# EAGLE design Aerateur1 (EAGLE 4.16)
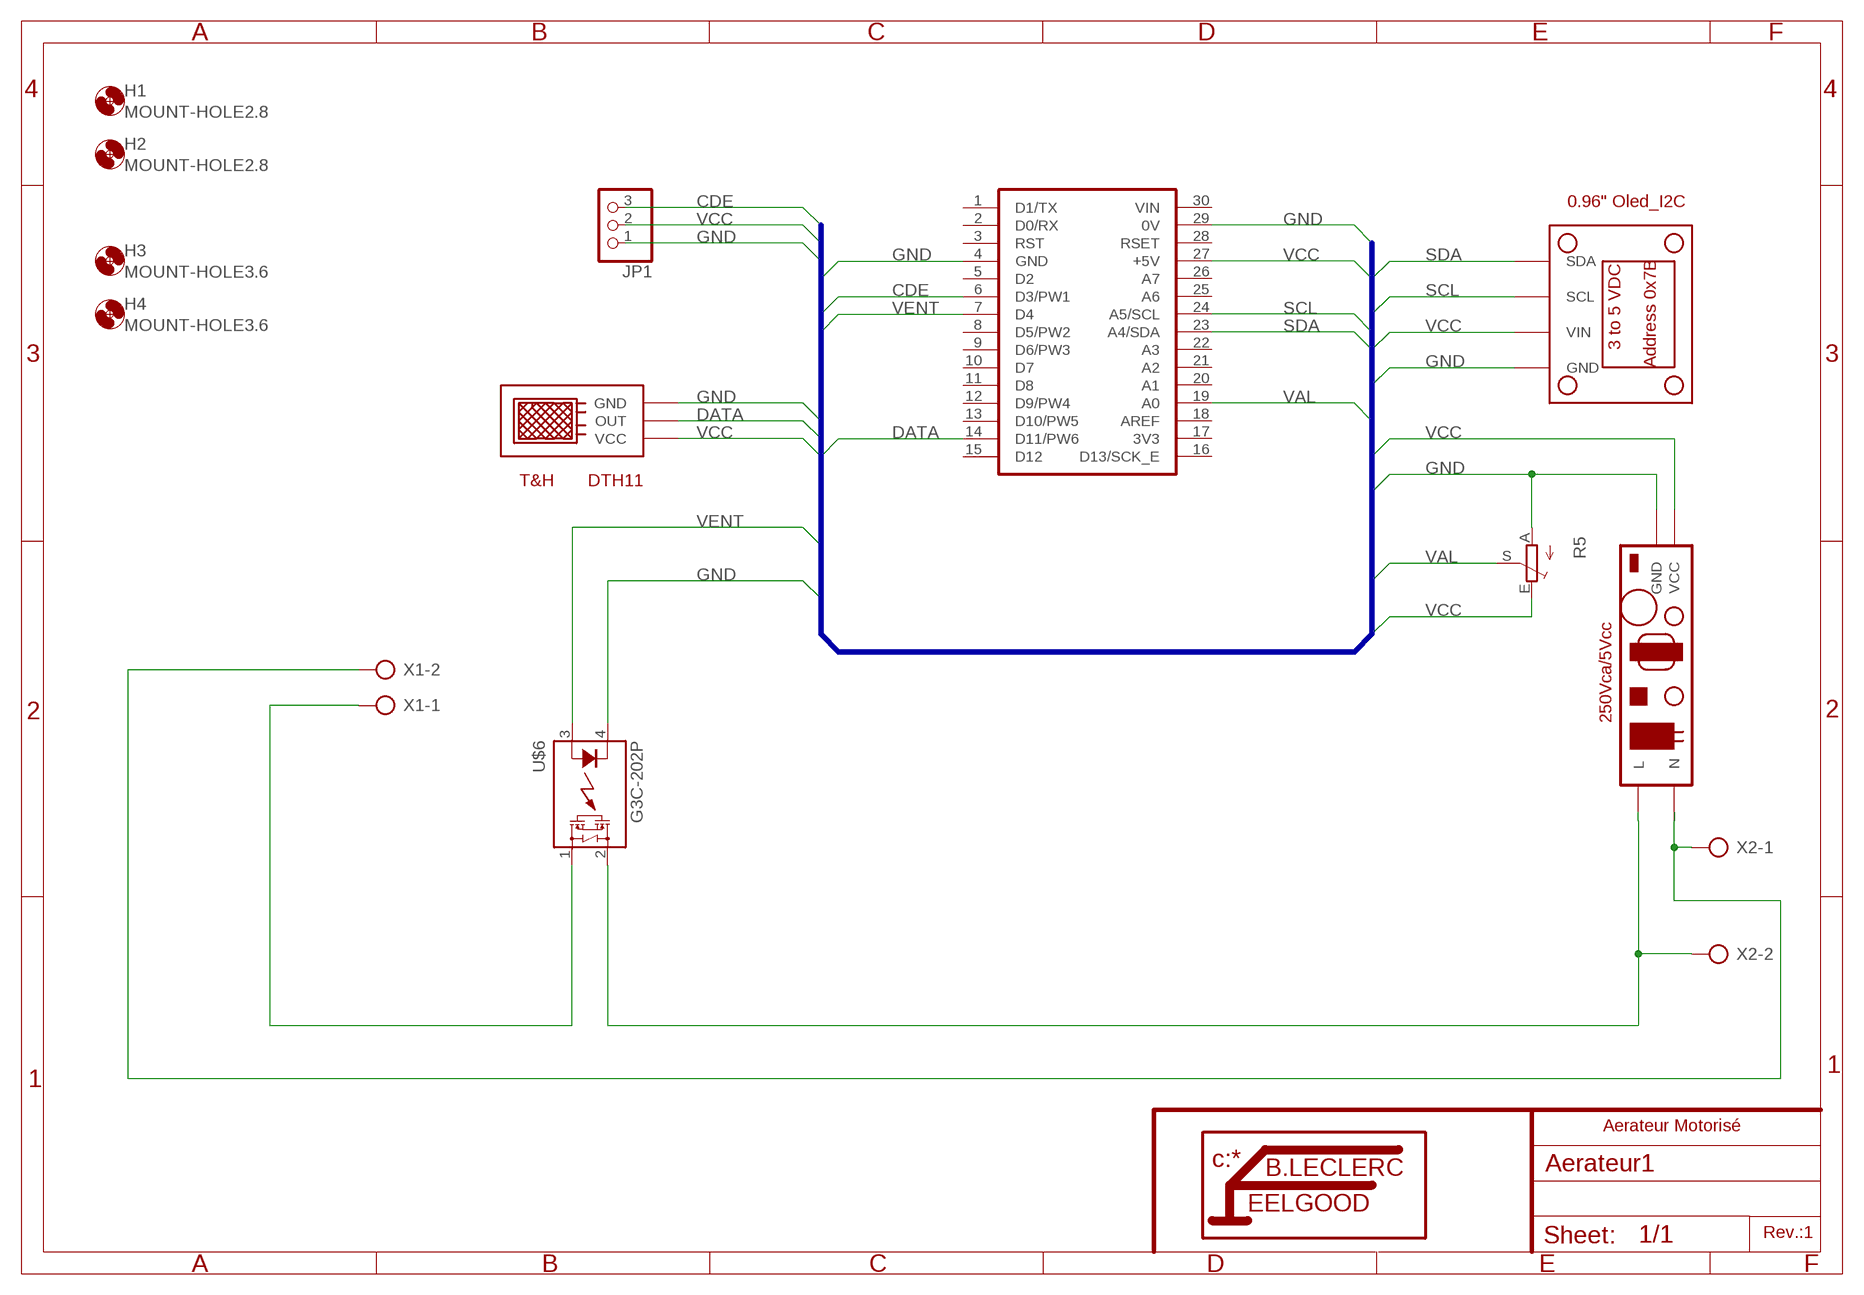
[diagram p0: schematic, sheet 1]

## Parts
H1  MOUNT-HOLE2.8  [2,8]
H2  MOUNT-HOLE2.8  [2,8]
H3  MOUNT-HOLE3.6  [3,6]
H4  MOUNT-HOLE3.6  [3,6]
JP1  PINHD-1X3  [1X03]
R5  TRIM_EU-S63S  [S63S]
U1  NANO  [NANO]
U$2  SWPWR250-5ALIM  [SWPWR250-5ALIM]
U$3  OLED_I2C_DISPLAY  [OLED_I2C_DISPLAY]
U$4  DTH11  [DTH11]
U$6  G3C-202P  [G3C-202P]
X1  AK300/2  [AK300/2]
X2  AK300/2  [AK300/2]

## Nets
CDE: JP1.3 U1.6(D3/PW1)
DATA: U1.14(D11/PW6) U$4.OUT
GND: JP1.1 R5.A U1.4(GND) U1.29(0V) U$2.GND U$3.GND U$4.GND U$6.4(K)
N$1: U$6.1(DS1) X1.1
N$4: U$2.L U$6.2(DS2) X2.2
N$9: U$2.N X1.2 X2.1
SCL: U1.24(A5/SCL) U$3.SCL
SDA: U1.23(A4/SDA) U$3.SDA
VAL: R5.S U1.19(A0)
VCC: JP1.2 R5.E U1.27(+5V) U$2.VCC U$3.VIN U$4.VCC
VENT: U1.7(D4) U$6.3(A)
Unconnected: U1.1(D1/TX) U1.2(D0/RX) U1.3(RST) U1.5(D2) U1.8(D5/PW2) U1.9(D6/PW3) U1.10(D7) U1.11(D8) U1.12(D9/PW4) U1.13(D10/PW5) U1.15(D12) U1.16(D13/SCK_E) U1.18(AREF) U1.20(A1) U1.21(A2) U1.22(A3) U1.25(A6) U1.26(A7) U1.28(RSET)

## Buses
B$1

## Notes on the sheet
- Aerateur Motorisé
- Rev.:1

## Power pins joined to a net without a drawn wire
3V3: U1.17(3V3)
VIN: U1.30(VIN)

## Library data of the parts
H1-H4 = holes:MOUNT-HOLE: MOUNTING HOLE with drill center marker
JP1 = pinhead:PINHD-1X3: PIN HEADER
R5 = pot:TRIM_EU-: POTENTIOMETER
U1 = Arduino:NANO
U$2 = Arduino:SWPWR250-5ALIM
U$3 = Arduino:OLED_I2C_DISPLAY
U$4 = Arduino:DTH11
U$6 = relay:G3C-202P
X1 X2 = con-ptr500:AK300/2: CONNECTOR

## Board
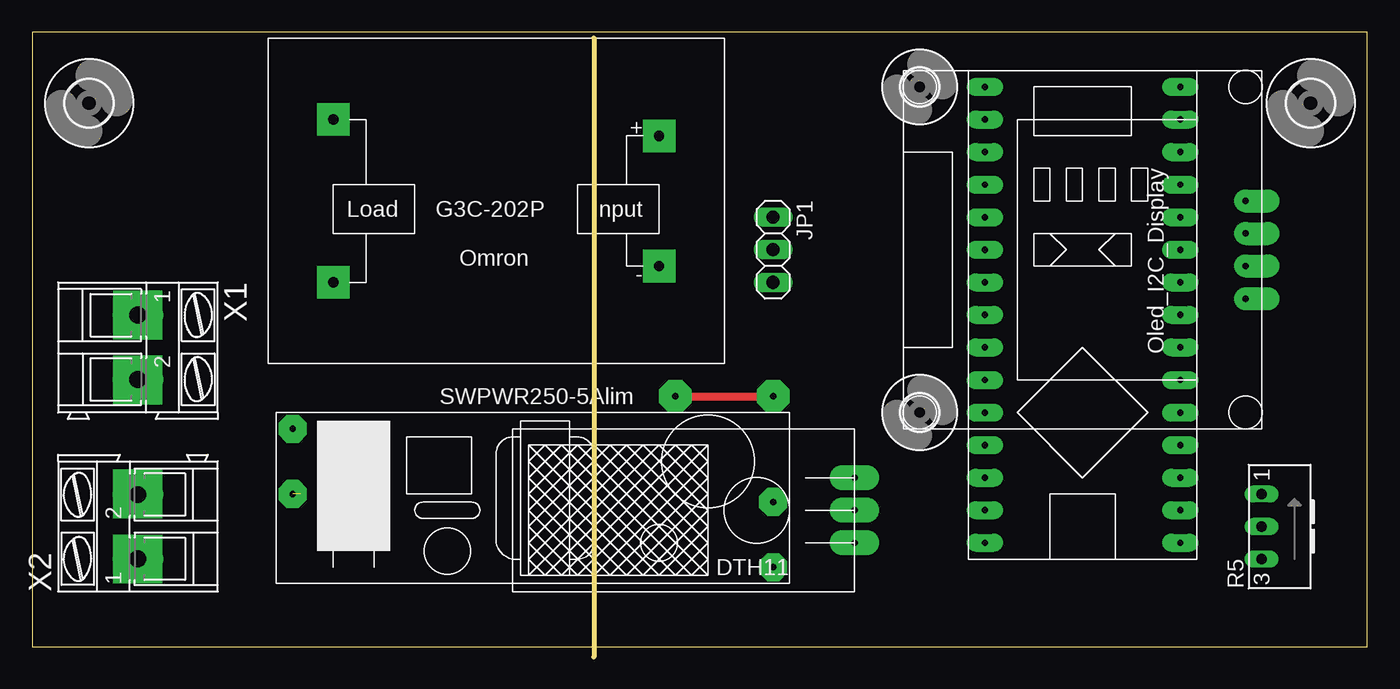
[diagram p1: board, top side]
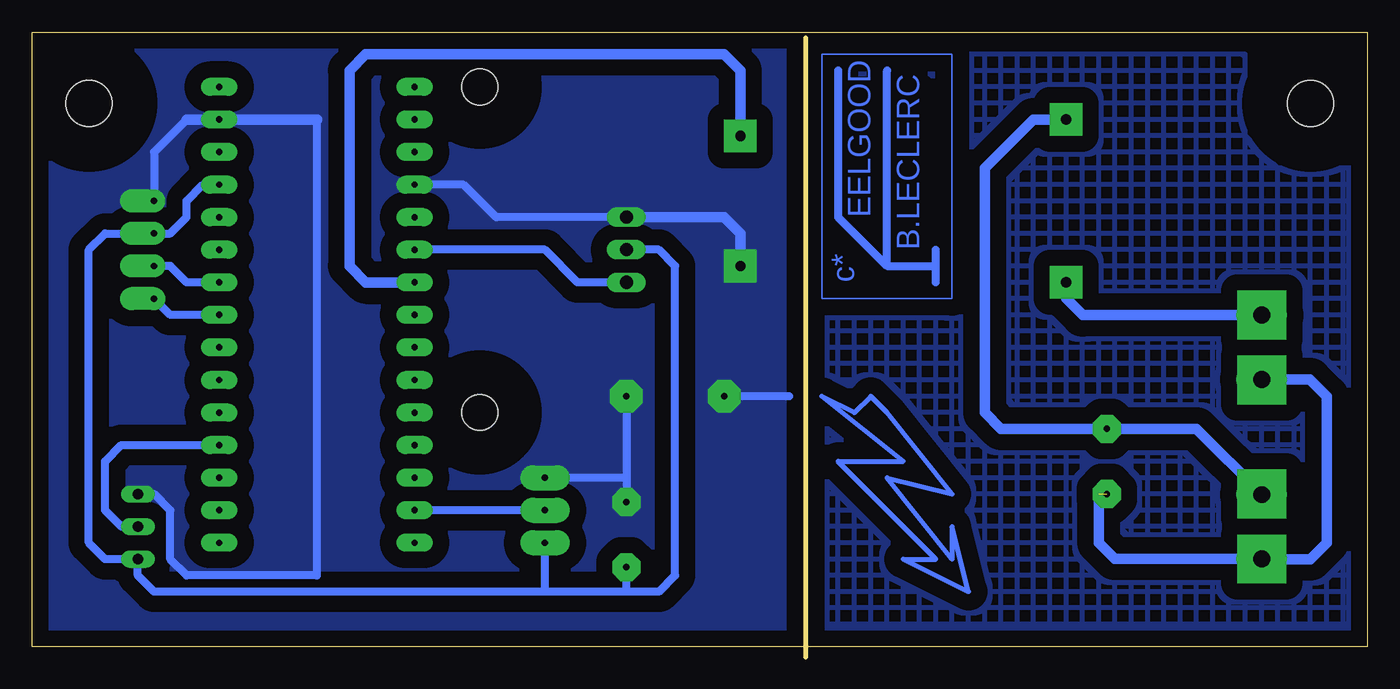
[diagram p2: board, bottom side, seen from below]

Size 104.12 x 48.73 mm. Coordinates in mm from the lower left corner, seen from the top.
Outline: 43.81,48.26 43.81,0
Outline: 0,0.8 104.12,0.8 104.12,48.73 0,48.73 0,0.8
Copper layers (1*16): Top 0.035mm / dielectric 1.5mm / Bottom 0.035mm
Design rules "default": minimum track width 10mil, minimum drill 24mil, track to track 8mil, track to pad 8mil, pad to pad 8mil, via to via 8mil, smd to smd 8mil, copper to edge 40mil, drill to drill 8mil, minimum pad ring 10mil, minimum via ring 8mil, stop-mask expansion 4mil, vias tented up to drill 0mil, thermal gap 10mil

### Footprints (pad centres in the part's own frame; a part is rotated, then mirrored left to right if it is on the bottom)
2,8 = hole 2.8: 0,0
3,6 = hole 3.6: 0,0
1X03 = drill 1.016 long: 1 -2.54,0; 2 0,0; 3 2.54,0
S63S = drill 0.813 long: A 2.54,1.27; E -2.54,1.27; S 0,1.27
NANO = drill 0.5 pad 1.422 long: 1 -7.62,17.78; 2 -7.62,15.24; 3 -7.62,12.7; 4 -7.62,10.16; 5 -7.62,7.62; 6 -7.62,5.08; 7 -7.62,2.54; 8 -7.62,0; 9 -7.62,-2.54; 10 -7.62,-5.08; 11 -7.62,-7.62; 12 -7.62,-10.16; 13 -7.62,-12.7; 14 -7.62,-15.24; 15 -7.62,-17.78; 16 7.62,-17.78; 17 7.62,-15.24; 18 7.62,-12.7; 19 7.62,-10.16; 20 7.62,-7.62; 21 7.62,-5.08; 22 7.62,-2.54; 23 7.62,0; 24 7.62,2.54; 25 7.62,5.08; 26 7.62,7.62; 27 7.62,10.16; 28 7.62,12.7; 29 7.62,15.24; 30 7.62,17.78
SWPWR250-5ALIM = drill 0.5 pad 2.184 octagon: GND 19.05,-0.635; L -18.415,5.08; N -18.415,0; VCC 19.05,-5.715
OLED_I2C_DISPLAY = drill 0.5 pad 1.778 offset: GND 10.16,26.67; SCL 15.24,26.67; SDA 17.78,26.67; VIN 12.7,26.67
DTH11 = drill 0.5 pad 1.93 long: GND -5.08,-2.54; OUT -5.08,0; VCC -5.08,2.54
G3C-202P = drill 0.8 pad 2.54 square: 1 25.4,6.35; 2 25.4,-6.35; 3 0,-5.08; 4 0,5.08
AK300/2 = drill 1.321 long: 1 -2.515,0; 2 2.489,0

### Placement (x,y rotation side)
H1  69.21,44.45 0 top
H2  69.21,19.05 0 top
H3  4.44,43.18 0 top
H4  99.69,43.18 0 top
JP1  57.78,31.75 270 top
R5  97.15,10.16 90 top
U1  81.91,26.67 0 top
U$2  38.73,12.7 0 top
U$3  67.94,45.72 270 top
U$4  59.05,11.43 180 top
U$5  [LITTFEEL]  29.84,30.48 90 bottom
U$6  48.89,35.56 180 top
X1  8.25,24.13 270 top
X2  8.25,10.16 90 top

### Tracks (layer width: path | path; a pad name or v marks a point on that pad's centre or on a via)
CDE
  Bottom 0.61: U1.6 64.13,31.75 61.59,29.21 JP1.3
DATA
  Bottom 0.61: U$4.OUT U1.14
GND  (via drill 0.5 pad 1.27, 0.5 pad 2.54)
  Top 0.61: v50.16,20.32 v57.78,20.32
  Bottom 0.61: 57.78,13.97 U$4.GND | 57.78,13.97 57.78,11.43 | JP1.1 67.94,34.29 70.48,36.83 U1.4 | R5.A 94.61,12.7 93.34,11.43 93.34,7.62 92.07,6.35 81.91,6.35 81.91,41.91 | 92.07,41.91 94.61,39.37 U$3.GND | v57.78,20.32 57.78,13.97 | 45.08,20.32 v50.16,20.32
  Bottom 0.813: 81.91,41.91 U1.29 92.07,41.91 | U$6.4 48.89,33.02 50.16,34.29 JP1.1
  other vias: 57.78,34.29 95.88,12.7
  pour Bottom (isolate 1.27, no thermals): 45.08,1.27 45.08,48.26 103.5,48.26 103.5,1.27
N$1
  Bottom 0.813: X1.1 22.2,26.64 23.49,27.94 U$6.1
N$3  (via drill 0.5 pad 3.81)
  other vias: 8.25,26.67
N$4
  Bottom 0.813: 19.68,17.78 13.33,17.78 8.25,12.7 X2.2 | 19.68,17.78 U$2.L | 19.68,17.78 28.57,17.78 29.84,19.05 29.84,38.1 26.03,41.91 U$6.2
N$8  (via drill 0.5 pad 3.81)
  other vias: 8.25,21.59
N$9  (1 unrouted)
  Bottom 0.813: 20.95,12.7 20.95,8.89 19.7,7.64 X2.1 8.25,7.62 4.44,7.62 3.17,8.89 3.17,20.32 4.49,21.64 X1.2 8.25,21.59
N$10  (via drill 0.5 pad 3.81)
  other vias: 8.25,12.7
N$11  (via drill 0.5 pad 3.81)
  other vias: 8.25,7.62
N$16
  pour Bottom (isolate 1.27, no thermals, hatched): 0.63,38.1 6.98,38.1 9.52,40.64 9.52,46.99 43.81,46.99 43.81,1.27 0.63,1.27
N$22  (via drill 0.5 pad 1.27)
  other vias: 57.78,31.75
N$23  (via drill 0.5 pad 1.27)
  other vias: 57.78,29.21
N$25  (via drill 0.5 pad 1.27)
  other vias: 95.88,10.16
N$26  (via drill 0.5 pad 1.27)
  other vias: 95.88,7.62
N$37
  Bottom 0.406: 32.38,12.7 37.46,19.05 38.73,20.32 40,19.05 42.54,20.32 36.19,15.24 41.27,15.24 33.65,7.62 36.19,7.62 31.11,5.08 32.38,10.16 32.38,7.62 37.46,13.97 32.38,12.7
SCL
  Bottom 0.61: U1.24 92.07,29.21 93.34,30.48 U$3.SCL
SDA
  Bottom 0.61: U1.23 93.34,26.67 U$3.SDA
VAL
  Bottom 0.61: U1.19 97.15,16.51 98.42,15.24 98.42,11.43 97.15,10.16 R5.S
VCC
  Bottom 0.61: 57.78,5.08 U$2.VCC | 57.78,5.08 64.13,5.08 | 64.13,5.08 94.61,5.08 95.88,6.35 R5.E 98.42,7.62 99.69,8.89 99.69,31.75 98.42,33.02 U$3.VIN 93.34,33.02 92.07,34.29 92.07,35.56 90.8,36.83 U1.27 | 64.13,5.08 U$4.VCC | JP1.2 55.24,31.75 53.97,30.48 53.97,6.35 55.24,5.08 57.78,5.08
VENT
  Bottom 0.813: U1.7 78.1,29.21 79.37,30.48 79.37,45.72 78.1,46.99 50.16,46.99 48.89,45.72 U$6.3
